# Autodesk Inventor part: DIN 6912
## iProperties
Shininess: 64.0
Length Units: 11269
Angle Units: 11279
Time Units: 11290
Mass Units: 11283
Length Display Precision: 4
Angle Display Precision: 2
Compacted: True
Created: 2002-08
Part Number: DIN 6912
Material: Grade 8.8
Description: Inbusbout DIN 6912 - M10x25
Document SubType Name: Modeling
Designer: Cor de Vlaming
Engineer: Cor de Vlaming
Density: 0.0
Volumn: 0.0
Area: 0.0
PropertySet Name: Model Information
Control State: 0
Master: False
Checked Out: False
Author: Cor de Vlaming
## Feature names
1. Extrusion1
2. Extrusion2
3. Extrusion3
4. Hole1
5. Fillet1
6. Chamfer2
7. Fillet2
